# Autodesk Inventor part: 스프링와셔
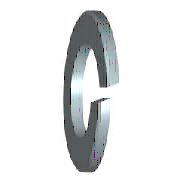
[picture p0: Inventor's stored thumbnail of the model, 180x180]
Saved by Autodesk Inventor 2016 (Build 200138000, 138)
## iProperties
IsCustomPart: 1
Created: 2012-02
Part Number: 스프링와셔
Material: 강철, 연강
Description: 스프링 와셔
Document SubType Name: Modeling
Standard: JIS B 1251
Designer: mduedu
Standards Organization: JIS
Language: ko-KR
Size Designation: 번호 2 4
Categories: <MemberInstance><Categories><Category DisplayName="조임쇠" InternalName="e4da775c-781d-43d5-af7c-5136215cf5a6" Mnemonic="FSTN"><Category DisplayName="와셔" InternalN
Density: 1 g/cm^3
Appearance: 파란색 - 벽 페인트 - 광택
Author: mduedu
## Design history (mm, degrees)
sketch "스케치1"
  geometry: C1 r 3.8 at (0, 0); C2 r 2.05 at (0, 0); 1 further point
  constraints: 2 centre point, 2 coincident
  dimensions: "d0" = 4.1 diameter of C2 (= SD1); "d1" = 7.6 diameter of C1 (= SD2)
extrude "본체" new body sketch "스케치1" distance "d2" = 1 (= SD); taper "d3" = 0 deg
sketch "스케치2"
  geometry: L1 (0, -2.05)-(0, 2.05) reference; L2 (1, 3.8)-(1, -3.8) reference; L3 (-1.2, 0)-(7.2, 0) reference; L4 (0, -0.2)-(1, 0.164); L5 (0, 0.2)-(1, 0.564)
  constraints: 4 end point, 4 point on line, 1 parallel
  dimensions: "d4" = 0.2 distance from line of L3 L4.start (= 0.2 x SD); "d5" = 0.2 distance from line of L3 L5.start (= 0.2 x SD); "d6" = 70 deg angle of L2 L4 (= FAWI)
extrude "절단부" cut sketch "스케치2" stored distance "d7" = 1 (= SD); taper "d8" = 0 deg
workaxis "Work Axis1"
workplane "Work Plane1"
body "Solid1"
other parameters: "SD1" = 4.1 [user parameter; used in 1 equation term], "SD2" = 7.6 [user parameter; used in 1 equation term], "SD" = 1 [user parameter; used in 4 equation terms], "FAWI" = 70 deg [user parameter; used in 1 equation term], "d9" = 0, "d10" = 0, "d11" = 0, "d12" = 0, "SDI" = 1.4 [user parameter], "NND" = 4 [user parameter]
